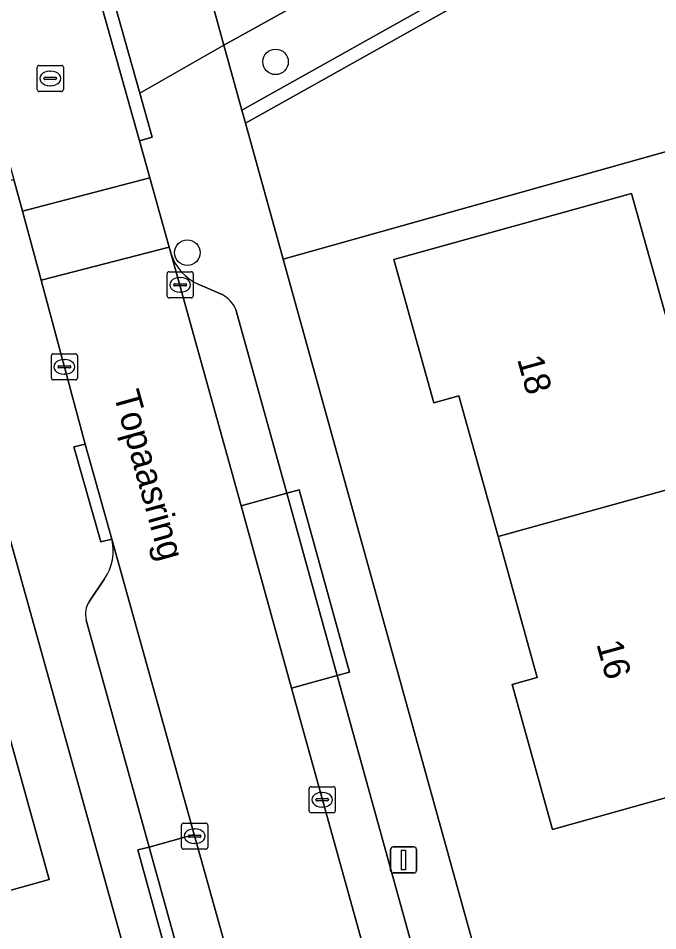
# Model space of a CAD drawing. Extents: x 159626 to 160723, y 388173 to 389416.
# Drawn here: x 160136.62 to 160161.1, y 388430.02 to 388464.98 of the extents above; entities that cross this region are included whole.
import ezdxf

# ---------------------------------------------------------------- set-up
doc = ezdxf.new("R2010")
doc.units = 0
for name, color, linetype in [('IMGEO_Berm_groen', 7, 'Continuous'), ('IMGEO_Boom', 7, 'Continuous'), ('IMGEO_Erf', 7, 'Continuous'), ('IMGEO_Groenvoorziening', 7, 'Continuous'), ('IMGEO_Haag', 7, 'Continuous'), ('IMGEO_Hek', 7, 'Continuous'), ('IMGEO_Kolk', 7, 'Continuous'), ('IMGEO_Lichtmast', 7, 'Continuous'), ('IMGEO_Openbare_ruimte_label', 7, 'Continuous'), ('IMGEO_Pand', 7, 'Continuous'), ('IMGEO_Pand_nummerreeks', 7, 'Continuous'), ('IMGEO_Parkeervlak_open', 7, 'Continuous'), ('IMGEO_Rijbaan_lokaal_open', 7, 'Continuous'), ('IMGEO_Rioolput', 7, 'Continuous'), ('IMGEO_Voetpad_open', 7, 'Continuous')]:
    doc.layers.add(name, color=color, linetype=linetype)

msp = doc.modelspace()

# ---------------------------------------------------------------- linework, layer by layer
at = {"layer": 'IMGEO_Berm_groen'}
msp.add_lwpolyline([(160170.636, 388475.72), (160169.54, 388477.832), (160144.491, 388463.944), (160145.181, 388461.454)], close=True, dxfattribs=at)
at = {"layer": 'IMGEO_Boom'}
for centre in [(160146.47, 388463.308), (160143.092, 388455.998)]:
    msp.add_circle(centre, 0.489, dxfattribs=at)
at = {"layer": 'IMGEO_Erf'}
for points in [[(160194.8, 388432.52), (160197.128, 388432.669), (160196.924, 388435.851), (160175.46, 388434.431), (160172.81, 388443.88), (160164.747, 388441.621), (160166.19, 388436.47), (160161.893, 388435.258), (160157.08, 388433.9), (160155.53, 388439.45), (160156.492, 388439.717), (160154.989, 388445.122), (160153.492, 388450.507), (160152.53, 388450.24), (160151, 388455.73), (160160.104, 388458.264), (160161.537, 388453.115), (160169.64, 388455.37), (160167.851, 388461.677), (160146.76, 388455.755), (160154.009, 388429.596), (160157.756, 388416.075), (160158.642, 388412.875)], [(160145.423, 388412.242), (160135.774, 388446.888)], [(160129.046, 388429.622), (160127.463, 388435.235), (160125.871, 388440.88), (160122.793, 388440.012), (160121.928, 388443.082), (160128.374, 388444.925), (160129.221, 388441.922), (160134.607, 388443.442), (160136.214, 388437.688), (160137.808, 388431.979), (160132.438, 388430.488), (160133.26, 388427.562)]]:
    msp.add_lwpolyline(points, dxfattribs=at)
at = {"layer": 'IMGEO_Groenvoorziening'}
for points in [[(160145.318, 388460.958), (160170.867, 388475.276), (160170.636, 388475.72), (160145.181, 388461.454)], [(160172.544, 388456.178), (160170.208, 388464.53), (160174.883, 388467.539), (160170.867, 388475.276), (160145.318, 388460.958), (160146.76, 388455.755), (160167.851, 388461.677), (160169.64, 388455.37)]]:
    msp.add_lwpolyline(points, close=True, dxfattribs=at)
at = {"layer": 'IMGEO_Haag'}
msp.add_lwpolyline([(160145.318, 388460.958), (160170.867, 388475.276), (160170.636, 388475.72), (160145.181, 388461.454)], close=True, dxfattribs=at)
at = {"layer": 'IMGEO_Hek'}
msp.add_lwpolyline([(160146.76, 388455.755), (160167.851, 388461.677)], dxfattribs=at)
at = {"layer": 'IMGEO_Kolk'}
for p, q in [((160142.317, 388454.341), (160142.317, 388455.193)), ((160142.392, 388455.267), (160143.244, 388455.267)), ((160142.805, 388455.047), (160142.83, 388455.047)), ((160143.318, 388455.193), (160143.318, 388454.341)), ((160142.576, 388454.761), (160142.576, 388454.773)), ((160143.014, 388454.724), (160142.616, 388454.724)), ((160142.619, 388454.81), (160143.017, 388454.81)), ((160143.06, 388454.773), (160143.06, 388454.761)), ((160143.244, 388454.267), (160142.392, 388454.267)), ((160142.828, 388454.487), (160142.803, 388454.487)), ((160137.885, 388451.197), (160137.885, 388452.049)), ((160137.96, 388452.123), (160138.812, 388452.123)), ((160138.373, 388451.903), (160138.398, 388451.903)), ((160138.886, 388452.049), (160138.886, 388451.197)), ((160138.144, 388451.617), (160138.144, 388451.629)), ((160138.582, 388451.58), (160138.184, 388451.58)), ((160138.187, 388451.666), (160138.585, 388451.666)), ((160138.628, 388451.629), (160138.628, 388451.617)), ((160138.812, 388451.123), (160137.96, 388451.123)), ((160138.396, 388451.343), (160138.371, 388451.343)), ((160147.755, 388434.615), (160147.755, 388435.467)), ((160147.83, 388435.541), (160148.682, 388435.541)), ((160148.756, 388435.467), (160148.756, 388434.615)), ((160148.014, 388435.035), (160148.014, 388435.047)), ((160148.057, 388435.084), (160148.455, 388435.084)), ((160148.243, 388435.321), (160148.268, 388435.321)), ((160148.498, 388435.047), (160148.498, 388435.035)), ((160148.452, 388434.998), (160148.054, 388434.998)), ((160148.266, 388434.761), (160148.241, 388434.761)), ((160148.682, 388434.541), (160147.83, 388434.541)), ((160142.873, 388433.219), (160142.873, 388434.071)), ((160142.948, 388434.145), (160143.8, 388434.145)), ((160143.874, 388434.071), (160143.874, 388433.219)), ((160143.132, 388433.639), (160143.132, 388433.651)), ((160143.57, 388433.602), (160143.172, 388433.602)), ((160143.175, 388433.688), (160143.573, 388433.688)), ((160143.361, 388433.925), (160143.386, 388433.925)), ((160143.616, 388433.651), (160143.616, 388433.639)), ((160143.384, 388433.365), (160143.359, 388433.365)), ((160143.8, 388433.145), (160142.948, 388433.145))]:
    msp.add_line(p, q, dxfattribs=at)
for points in [[(160142.317, 388454.341), (160142.317, 388455.193)], [(160142.392, 388455.267), (160143.244, 388455.267)], [(160143.318, 388455.193), (160143.318, 388454.341)], [(160143.244, 388454.267), (160142.392, 388454.267)], [(160137.885, 388451.197), (160137.885, 388452.049)], [(160137.96, 388452.123), (160138.812, 388452.123)], [(160138.886, 388452.049), (160138.886, 388451.197)], [(160138.812, 388451.123), (160137.96, 388451.123)], [(160147.755, 388434.615), (160147.755, 388435.467)], [(160147.83, 388435.541), (160148.682, 388435.541)], [(160148.756, 388435.467), (160148.756, 388434.615)], [(160148.682, 388434.541), (160147.83, 388434.541)], [(160142.873, 388433.219), (160142.873, 388434.071)], [(160142.948, 388434.145), (160143.8, 388434.145)], [(160143.874, 388434.071), (160143.874, 388433.219)], [(160143.8, 388433.145), (160142.948, 388433.145)]]:
    msp.add_lwpolyline(points, dxfattribs=at)
for centre, radius, start, end in [((160142.394, 388455.191), 0.0765, 91.552, 178.448), ((160142.394, 388455.191), 0.0765, 91.552, 178.448), ((160143.242, 388455.191), 0.0765, 1.552, 88.448), ((160143.242, 388455.191), 0.0765, 1.552, 88.448), ((160142.616, 388454.77), 0.0403, 85.8775, 175.7526), ((160142.613, 388454.76), 0.0366, 178.938, 274.7102), ((160143.017, 388454.767), 0.043, 264.8664, 352.4533), ((160143.021, 388454.772), 0.0386, 1.7309, 96.639), ((160142.394, 388454.343), 0.0765, 181.552, 268.448), ((160142.394, 388454.343), 0.0765, 181.552, 268.448), ((160143.242, 388454.343), 0.0765, 271.552, 358.448), ((160143.242, 388454.343), 0.0765, 271.552, 358.448), ((160137.962, 388452.047), 0.0765, 91.552, 178.448), ((160137.962, 388452.047), 0.0765, 91.552, 178.448), ((160138.81, 388452.047), 0.0765, 1.552, 88.448), ((160138.81, 388452.047), 0.0765, 1.552, 88.448), ((160138.184, 388451.626), 0.0403, 85.8775, 175.7526), ((160138.181, 388451.616), 0.0366, 178.938, 274.7102), ((160138.585, 388451.623), 0.043, 264.8664, 352.4533), ((160138.589, 388451.628), 0.0386, 1.7309, 96.639), ((160137.962, 388451.199), 0.0765, 181.552, 268.448), ((160137.962, 388451.199), 0.0765, 181.552, 268.448), ((160138.81, 388451.199), 0.0765, 271.552, 358.448), ((160138.81, 388451.199), 0.0765, 271.552, 358.448), ((160147.832, 388435.465), 0.0765, 91.552, 178.448), ((160147.832, 388435.465), 0.0765, 91.552, 178.448), ((160148.68, 388435.465), 0.0765, 1.552, 88.448), ((160148.68, 388435.465), 0.0765, 1.552, 88.448), ((160148.054, 388435.044), 0.0403, 85.8775, 175.7526), ((160148.051, 388435.034), 0.0366, 178.938, 274.7102), ((160148.455, 388435.041), 0.043, 264.8664, 352.4533), ((160148.459, 388435.046), 0.0386, 1.7309, 96.639), ((160147.832, 388434.617), 0.0765, 181.552, 268.448), ((160147.832, 388434.617), 0.0765, 181.552, 268.448), ((160148.68, 388434.617), 0.0765, 271.552, 358.448), ((160148.68, 388434.617), 0.0765, 271.552, 358.448), ((160142.95, 388434.069), 0.0765, 91.552, 178.448), ((160142.95, 388434.069), 0.0765, 91.552, 178.448), ((160143.798, 388434.069), 0.0765, 1.552, 88.448), ((160143.798, 388434.069), 0.0765, 1.552, 88.448), ((160143.172, 388433.648), 0.0403, 85.8775, 175.7526), ((160143.169, 388433.638), 0.0366, 178.938, 274.7102), ((160143.573, 388433.645), 0.043, 264.8664, 352.4533), ((160143.577, 388433.65), 0.0386, 1.7309, 96.639), ((160142.95, 388433.221), 0.0765, 181.552, 268.448), ((160142.95, 388433.221), 0.0765, 181.552, 268.448), ((160143.798, 388433.221), 0.0765, 271.552, 358.448), ((160143.798, 388433.221), 0.0765, 271.552, 358.448)]:
    msp.add_arc(centre, radius, start, end, dxfattribs=at)
for centre, major_axis, ratio, start_param, end_param in [((160142.804, 388454.767), (-0.387, 0.002), 0.722429, 4.712389, 7.853982), ((160142.829, 388454.767), (-0.39, 0.002), 0.717154, 1.570796, 4.712389), ((160138.372, 388451.623), (-0.387, 0.002), 0.722429, 4.712389, 7.853982), ((160138.397, 388451.623), (-0.39, 0.002), 0.717154, 1.570796, 4.712389), ((160148.242, 388435.041), (-0.387, 0.002), 0.722429, 4.712389, 7.853982), ((160148.267, 388435.041), (-0.39, 0.002), 0.717154, 1.570796, 4.712389), ((160143.36, 388433.645), (-0.387, 0.002), 0.722429, 4.712389, 7.853982), ((160143.385, 388433.645), (-0.39, 0.002), 0.717154, 1.570796, 4.712389)]:
    msp.add_ellipse(centre, major_axis=major_axis, ratio=ratio, start_param=start_param, end_param=end_param, dxfattribs=at)
at = {"layer": 'IMGEO_Lichtmast'}
for p, q in [((160150.875, 388432.334), (160150.875, 388433.134)), ((160150.875, 388433.134), (160150.875, 388432.334)), ((160150.975, 388433.234), (160151.765, 388433.234)), ((160151.765, 388433.234), (160150.975, 388433.234)), ((160151.865, 388433.134), (160151.865, 388432.334)), ((160151.865, 388432.334), (160151.865, 388433.134)), ((160151.765, 388432.234), (160150.975, 388432.234)), ((160150.975, 388432.234), (160151.765, 388432.234))]:
    msp.add_line(p, q, dxfattribs=at)
msp.add_lwpolyline([(160151.295, 388433.109), (160151.445, 388433.109), (160151.445, 388432.359), (160151.295, 388432.359), (160151.295, 388433.109)], dxfattribs=at)
for centre, start, end in [((160150.975, 388433.134), 90, 180), ((160150.975, 388433.134), 90, 180), ((160151.765, 388433.134), 0, 90), ((160151.765, 388433.134), 360, 90), ((160150.975, 388432.334), 180, 270), ((160150.975, 388432.334), 180, 270), ((160151.765, 388432.334), 270, 0), ((160151.765, 388432.334), 270, 0)]:
    msp.add_arc(centre, 0.1, start, end, dxfattribs=at)
at = {"layer": 'IMGEO_Pand'}
for points in [[(160154.989, 388445.122), (160171.227, 388449.62), (160170.97, 388450.551), (160169.64, 388455.37), (160161.537, 388453.115), (160160.104, 388458.264), (160151, 388455.73), (160152.53, 388450.24), (160153.492, 388450.507)], [(160154.989, 388445.122), (160156.492, 388439.717), (160155.53, 388439.45), (160157.08, 388433.9), (160161.893, 388435.258), (160166.19, 388436.47), (160164.747, 388441.621), (160172.81, 388443.88), (160171.227, 388449.62)], [(160126.813, 388425.754), (160133.26, 388427.562), (160132.438, 388430.488), (160137.808, 388431.979), (160136.214, 388437.688), (160127.463, 388435.235), (160129.046, 388429.622), (160125.967, 388428.753)]]:
    msp.add_lwpolyline(points, close=True, dxfattribs=at)
at = {"layer": 'IMGEO_Parkeervlak_open'}
for points in [[(160142.477, 388455.934), (160145.15, 388446.295), (160146.896, 388446.779), (160144.95, 388453.818)], [(160144.421, 388454.389), (160143.503, 388454.79)], [(160139.224, 388441.917), (160141.631, 388433.226), (160143.358, 388433.706), (160140.207, 388445.019)], [(160139.919, 388443.498), (160139.344, 388442.649)], [(160148.825, 388439.798), (160147.085, 388439.316), (160153.525, 388416.089), (160154.242, 388413.556)], [(160155.242, 388416.638), (160148.825, 388439.798)]]:
    msp.add_lwpolyline(points, dxfattribs=at)
for points in [[(160146.896, 388446.779), (160145.15, 388446.295), (160147.085, 388439.316), (160148.825, 388439.798)], [(160143.358, 388433.706), (160141.631, 388433.226), (160143.442, 388426.686), (160145.188, 388427.134)]]:
    msp.add_lwpolyline(points, close=True, dxfattribs=at)
for centre, radius, start, end in [((160144.316, 388456.552), 1.94, 198.5586, 245.2163), ((160143.892, 388453.369), 1.149, 23.0166, 62.6103), ((160138.336, 388444.585), 1.921, 325.5105, 13.0455), ((160140.071, 388442.154), 0.879, 145.7452, 195.6349)]:
    msp.add_arc(centre, radius, start, end, dxfattribs=at)
at = {"layer": 'IMGEO_Rijbaan_lokaal_open'}
for points in [[(160263.316, 388534.528), (160261.564, 388533.543), (160201.121, 388500), (160168.517, 388481.906), (160166.882, 388480.998), (160143.387, 388467.946), (160144.491, 388463.944), (160169.54, 388477.832), (160171.15, 388478.728), (160186.841, 388487.459), (160188.084, 388485.211), (160188.326, 388484.773), (160188.594, 388484.287), (160188.827, 388483.868), (160197.07, 388488.397), (160196.581, 388489.269), (160195.04, 388492.014)], [(160147.085, 388439.316), (160145.15, 388446.295), (160142.477, 388455.934), (160142.401, 388456.206), (160137.494, 388454.941), (160139.186, 388448.658), (160140.207, 388445.019), (160143.358, 388433.706), (160145.188, 388427.134), (160148.059, 388416.828), (160149.064, 388413.184), (160149.324, 388412.243), (160149.559, 388411.487)], [(160154.848, 388411.443), (160154.242, 388413.556), (160153.525, 388416.089), (160147.085, 388439.316)]]:
    msp.add_lwpolyline(points, dxfattribs=at)
for points in [[(160130.149, 388500), (160127.356, 388510.063), (160127.238, 388510.351), (160121.847, 388510.533), (160131.543, 388476.115), (160133.41, 388469.46), (160134.433, 388465.953), (160136.455, 388458.799), (160136.782, 388457.586), (160141.656, 388458.87), (160141.26, 388460.286), (160139.386, 388466.972), (160138.44, 388470.191), (160136.156, 388478.361)], [(160139.867, 388467.106), (160139.386, 388466.972), (160141.26, 388460.286), (160141.741, 388460.42), (160141.27, 388462.102)], [(160142.401, 388456.206), (160141.656, 388458.87), (160136.782, 388457.586), (160137.494, 388454.941)]]:
    msp.add_lwpolyline(points, close=True, dxfattribs=at)
at = {"layer": 'IMGEO_Rioolput'}
for p, q in [((160137.344, 388462.246), (160137.344, 388463.098)), ((160137.419, 388463.172), (160138.271, 388463.172)), ((160138.345, 388463.098), (160138.345, 388462.246)), ((160137.603, 388462.666), (160137.603, 388462.678)), ((160138.041, 388462.629), (160137.643, 388462.629)), ((160137.646, 388462.715), (160138.044, 388462.715)), ((160137.832, 388462.952), (160137.857, 388462.952)), ((160138.087, 388462.678), (160138.087, 388462.666)), ((160137.855, 388462.392), (160137.83, 388462.392)), ((160138.271, 388462.172), (160137.419, 388462.172))]:
    msp.add_line(p, q, dxfattribs=at)
for points in [[(160137.344, 388462.246), (160137.344, 388463.098)], [(160137.419, 388463.172), (160138.271, 388463.172)], [(160138.345, 388463.098), (160138.345, 388462.246)], [(160138.271, 388462.172), (160137.419, 388462.172)]]:
    msp.add_lwpolyline(points, dxfattribs=at)
for centre, radius, start, end in [((160137.421, 388463.096), 0.0765, 91.552, 178.448), ((160137.421, 388463.096), 0.0765, 91.552, 178.448), ((160138.269, 388463.096), 0.0765, 1.552, 88.448), ((160138.269, 388463.096), 0.0765, 1.552, 88.448), ((160137.643, 388462.675), 0.0403, 85.8775, 175.7526), ((160137.64, 388462.665), 0.0366, 178.938, 274.7102), ((160138.044, 388462.672), 0.043, 264.8664, 352.4533), ((160138.048, 388462.677), 0.0386, 1.7309, 96.639), ((160137.421, 388462.248), 0.0765, 181.552, 268.448), ((160137.421, 388462.248), 0.0765, 181.552, 268.448), ((160138.269, 388462.248), 0.0765, 271.552, 358.448), ((160138.269, 388462.248), 0.0765, 271.552, 358.448)]:
    msp.add_arc(centre, radius, start, end, dxfattribs=at)
for centre, major_axis, ratio, start_param, end_param in [((160137.831, 388462.672), (-0.387, 0.002), 0.722429, 4.712389, 7.853982), ((160137.856, 388462.672), (-0.39, 0.002), 0.717154, 1.570796, 4.712389)]:
    msp.add_ellipse(centre, major_axis=major_axis, ratio=ratio, start_param=start_param, end_param=end_param, dxfattribs=at)
at = {"layer": 'IMGEO_Voetpad_open'}
for points in [[(160127.238, 388510.351), (160127.356, 388510.063), (160130.149, 388500), (160136.156, 388478.361), (160138.44, 388470.191), (160139.386, 388466.972), (160139.867, 388467.106), (160141.27, 388462.102), (160144.491, 388463.944), (160143.387, 388467.946), (160143.161, 388468.763), (160141.107, 388468.188), (160140.57, 388470.105), (160140.457, 388470.509), (160139.703, 388473.203), (160132.204, 388500)], [(160157.756, 388416.075), (160154.009, 388429.596), (160146.76, 388455.755), (160145.318, 388460.958), (160145.181, 388461.454), (160144.491, 388463.944), (160141.27, 388462.102), (160141.741, 388460.42), (160141.26, 388460.286), (160141.656, 388458.87), (160142.401, 388456.206), (160142.477, 388455.934)], [(160137.494, 388454.941), (160136.782, 388457.586), (160136.455, 388458.799), (160135.974, 388458.664), (160135.679, 388459.706), (160132.71, 388458.055), (160133.566, 388454.936), (160133.756, 388454.242), (160134.059, 388453.138), (160135.774, 388446.888), (160145.423, 388412.242)], [(160140.207, 388445.019), (160139.782, 388444.925), (160138.749, 388448.554), (160139.186, 388448.658), (160137.494, 388454.941)], [(160143.503, 388454.79), (160144.421, 388454.389)], [(160144.95, 388453.818), (160146.896, 388446.779), (160147.372, 388446.911), (160149.306, 388439.931), (160148.825, 388439.798), (160155.242, 388416.638)], [(160139.344, 388442.649), (160139.919, 388443.498)], [(160145.574, 388418.985), (160143.442, 388426.686), (160142.994, 388426.571), (160141.201, 388433.123), (160141.631, 388433.226), (160139.224, 388441.917)]]:
    msp.add_lwpolyline(points, dxfattribs=at)
for points in [[(160140.207, 388445.019), (160139.186, 388448.658), (160138.749, 388448.554), (160139.782, 388444.925)], [(160147.372, 388446.911), (160146.896, 388446.779), (160148.825, 388439.798), (160149.306, 388439.931)], [(160141.631, 388433.226), (160141.201, 388433.123), (160142.994, 388426.571), (160143.442, 388426.686)]]:
    msp.add_lwpolyline(points, close=True, dxfattribs=at)
for centre, radius, start, end in [((160144.316, 388456.552), 1.94, 198.5586, 245.2163), ((160143.892, 388453.369), 1.149, 23.0166, 62.6103), ((160138.336, 388444.585), 1.921, 325.5105, 13.0455), ((160140.071, 388442.154), 0.879, 145.7452, 195.6349)]:
    msp.add_arc(centre, radius, start, end, dxfattribs=at)

# ---------------------------------------------------------------- texts
at = {"layer": 'IMGEO_Openbare_ruimte_label'}
msp.add_text('Topaasring', height=1, rotation=285.5517, dxfattribs=at).set_placement((160140.26, 388450.572))
at = {"layer": 'IMGEO_Pand_nummerreeks'}
for s, p in [('18', (160155.713, 388451.922)), ('16', (160158.748, 388441.009))]:
    msp.add_text(s, height=1, rotation=285.5378, dxfattribs=at).set_placement(p)

doc.saveas('drawing.dxf')
